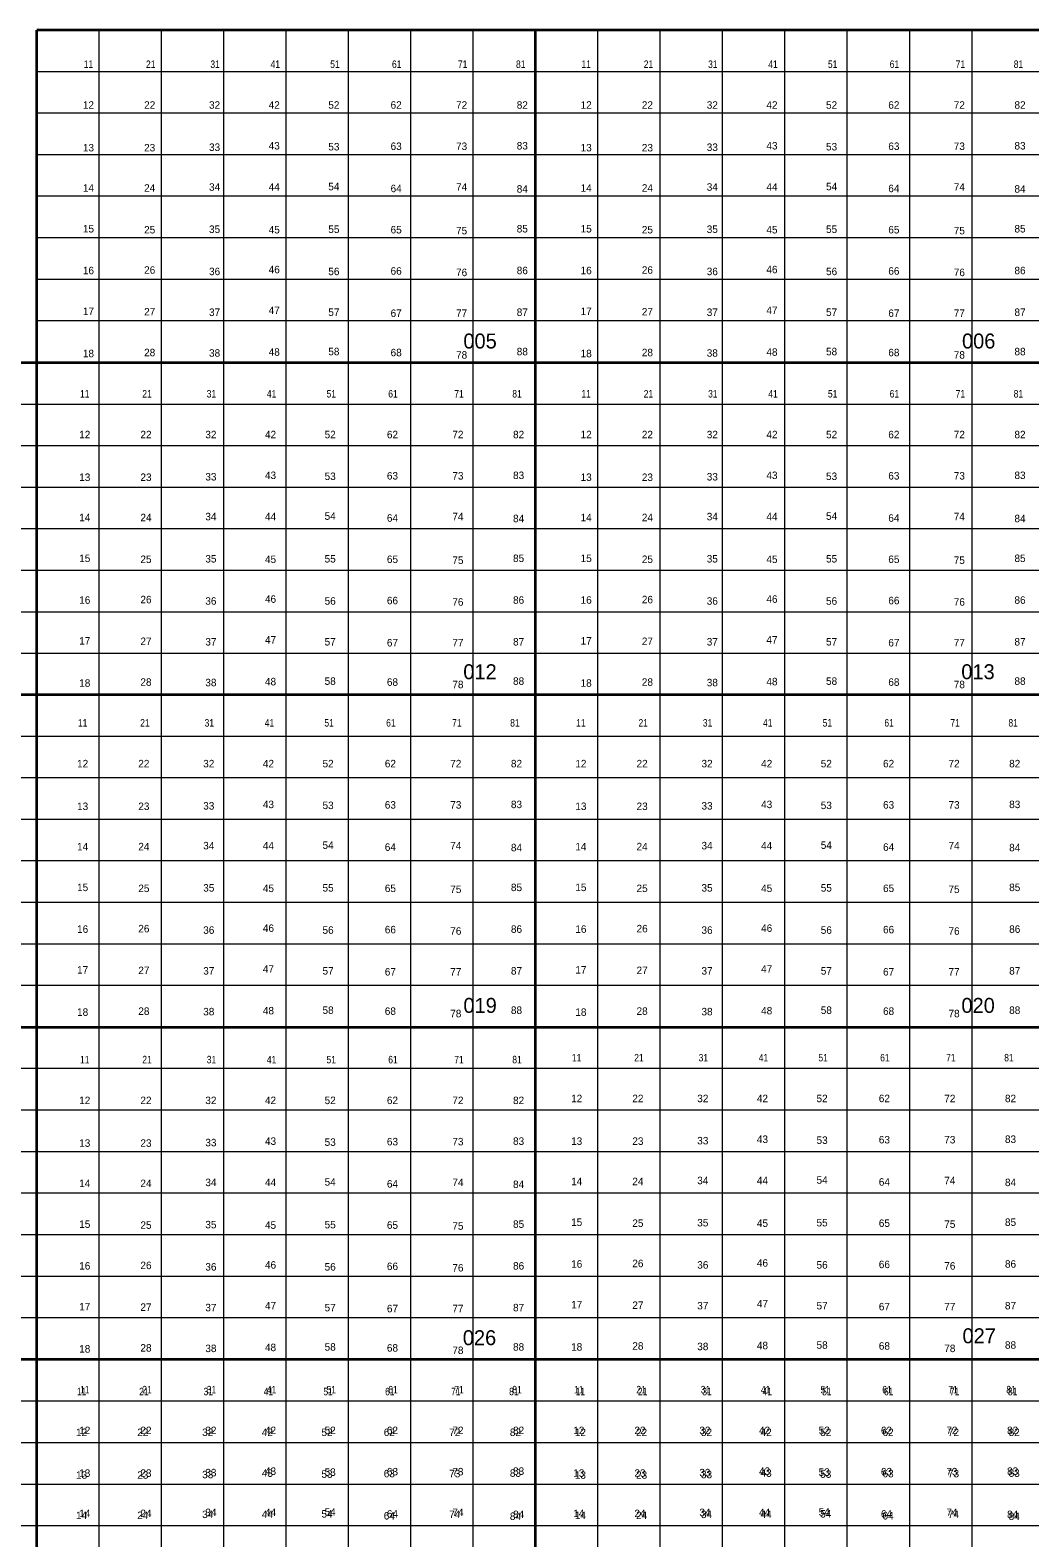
# Model space of a CAD drawing. Extents: x 639000 to 672000, y 222000 to 252000.
# Drawn here: x 647960 to 653973, y 242926 to 252000 of the extents above; entities that cross this region are included whole.
import ezdxf
from ezdxf.enums import TextEntityAlignment as Align

# ---------------------------------------------------------------- set-up
doc = ezdxf.new("R2010")
doc.units = 0
doc.header["$LTSCALE"] = 18
doc.layers.add('1', color=7, linetype='Continuous', lineweight=13)
doc.layers.add('2', color=7, linetype='Continuous')
doc.layers.add('29', color=7, linetype='Continuous')

msp = doc.modelspace()

# ---------------------------------------------------------------- linework, layer by layer
at = {"layer": '1', "lineweight": 35}
for p, q in [((657000, 252000), (648000, 252000)), ((648000, 224000), (648000, 252000)), ((651000, 224000), (651000, 252000)), ((645000, 250000), (657000, 250000)), ((660000, 248000), (639000, 248000)), ((639000, 246000), (663000, 246000)), ((666000, 244000), (639000, 244000))]:
    msp.add_line(p, q, dxfattribs=at)
at = {"layer": '1'}
for p, q in [((648375, 224000), (648375, 252000)), ((648750, 224000), (648750, 252000)), ((649125, 224000), (649125, 252000)), ((649500, 224000), (649500, 252000)), ((649875, 224000), (649875, 252000)), ((650250, 224000), (650250, 252000)), ((650625, 224000), (650625, 252000)), ((651375, 224000), (651375, 252000)), ((651750, 224000), (651750, 252000)), ((652125, 224000), (652125, 252000)), ((652500, 224000), (652500, 252000)), ((652875, 224000), (652875, 252000)), ((653250, 224000), (653250, 252000)), ((653625, 224000), (653625, 252000)), ((657000, 251750), (648000, 251750)), ((657000, 251500), (648000, 251500)), ((657000, 251250), (648000, 251250)), ((657000, 251000), (648000, 251000)), ((657000, 250750), (648000, 250750)), ((657000, 250500), (648000, 250500)), ((657000, 250250), (648000, 250250)), ((645000, 249750), (657000, 249750)), ((645000, 249500), (657000, 249500)), ((645000, 249250), (657000, 249250)), ((645000, 249000), (657000, 249000)), ((645000, 248750), (657000, 248750)), ((645000, 248500), (657000, 248500)), ((645000, 248250), (657000, 248250)), ((660000, 247750), (639000, 247750)), ((660000, 247500), (639000, 247500)), ((660000, 247250), (639000, 247250)), ((660000, 247000), (639000, 247000)), ((660000, 246750), (639000, 246750)), ((660000, 246500), (639000, 246500)), ((660000, 246250), (639000, 246250)), ((663000, 245750), (639000, 245750)), ((663000, 245500), (639000, 245500)), ((663000, 245250), (639000, 245250)), ((663000, 245000), (639000, 245000)), ((663000, 244750), (639000, 244750)), ((663000, 244500), (639000, 244500)), ((663000, 244250), (639000, 244250)), ((639000, 243750), (666000, 243750)), ((639000, 243500), (666000, 243500)), ((639000, 243250), (666000, 243250)), ((639000, 243000), (666000, 243000))]:
    msp.add_line(p, q, dxfattribs=at)

# ---------------------------------------------------------------- texts
at = {"layer": '2'}
for s, p in [('005', (650666.01, 250084.17)), ('006', (653665.16, 250084.17)), ('012', (650665.6, 248093.9)), ('013', (653660.9, 248093.9)), ('019', (650666.32, 246085.74)), ('020', (653661.69, 246085.74)), ('026', (650662.68, 244085.92))]:
    msp.add_text(s, height=90, dxfattribs=at).set_placement(p, align=Align.CENTER)
msp.add_text('027', height=90, rotation=359.94, dxfattribs=at).set_placement((653668.13, 244097.33), align=Align.CENTER)
at = {"layer": '29', "width": 0.85}
for s, p in [('11', (648310.53, 251772.53)), ('21', (648685.14, 251772.53)), ('31', (649072.44, 251772.53)), ('41', (649434.34, 251772.53)), ('51', (649793.08, 251772.53)), ('61', (650164.5, 251772.53)), ('71', (650561.33, 251772.53)), ('81', (650910.54, 251772.53)), ('11', (651304.19, 251772.53)), ('21', (651678.79, 251772.53)), ('31', (652066.09, 251772.53)), ('41', (652428, 251772.53)), ('51', (652786.73, 251772.53)), ('61', (653158.16, 251772.53)), ('71', (653554.98, 251772.53)), ('81', (653904.19, 251772.53)), ('11', (648288.31, 249789.2)), ('21', (648662.92, 249789.2)), ('31', (649050.22, 249789.2)), ('41', (649412.12, 249789.2)), ('51', (649770.85, 249789.2)), ('61', (650142.28, 249789.2)), ('71', (650539.11, 249789.2)), ('81', (650888.32, 249789.2)), ('11', (651304.19, 249789.2)), ('21', (651678.79, 249789.2)), ('31', (652066.09, 249789.2)), ('41', (652428, 249789.2)), ('51', (652786.73, 249789.2)), ('61', (653158.16, 249789.2)), ('71', (653554.98, 249789.2)), ('81', (653904.19, 249789.2)), ('11', (648275.61, 247808.76)), ('21', (648650.22, 247808.76)), ('31', (649037.52, 247808.76)), ('41', (649399.42, 247808.76)), ('51', (649758.15, 247808.76)), ('61', (650129.58, 247808.76)), ('71', (650526.41, 247808.76)), ('81', (650875.62, 247808.76)), ('11', (651272.44, 247808.76)), ('21', (651647.05, 247808.76)), ('31', (652034.35, 247808.76)), ('41', (652396.25, 247808.76)), ('51', (652754.98, 247808.76)), ('61', (653126.41, 247808.76)), ('71', (653523.24, 247808.76)), ('81', (653872.45, 247808.76)), ('11', (648288.31, 245782.12)), ('21', (648662.92, 245782.12)), ('31', (649050.22, 245782.12)), ('41', (649412.12, 245782.12)), ('51', (649770.85, 245782.12)), ('61', (650142.28, 245782.12)), ('71', (650539.11, 245782.12)), ('81', (650888.32, 245782.12)), ('11', (651247.05, 245793.67)), ('21', (651621.65, 245793.67)), ('31', (652008.95, 245793.67)), ('41', (652370.86, 245793.67)), ('51', (652729.59, 245793.67)), ('61', (653101.02, 245793.67)), ('71', (653497.84, 245793.67)), ('81', (653847.05, 245793.67)), ('11', (648269.26, 243784.35)), ('11', (648288.31, 243795.9)), ('21', (648643.86, 243784.35)), ('21', (648662.92, 243795.9)), ('31', (649031.16, 243784.35)), ('31', (649050.22, 243795.9)), ('41', (649393.07, 243784.35)), ('41', (649412.12, 243795.9)), ('51', (649751.8, 243784.35)), ('51', (649770.85, 243795.9)), ('61', (650123.23, 243784.35)), ('61', (650142.28, 243795.9)), ('71', (650520.05, 243784.35)), ('71', (650539.11, 243795.9)), ('81', (650869.26, 243784.35)), ('81', (650888.32, 243795.9)), ('11', (651259.74, 243795.9)), ('11', (651269.26, 243784.35)), ('21', (651634.35, 243795.9)), ('21', (651643.86, 243784.35)), ('31', (652021.65, 243795.9)), ('31', (652031.16, 243784.35)), ('41', (652383.55, 243795.9)), ('41', (652393.07, 243784.35)), ('51', (652742.29, 243795.9)), ('51', (652751.8, 243784.35)), ('61', (653113.71, 243795.9)), ('61', (653123.23, 243784.35)), ('71', (653510.54, 243795.9)), ('71', (653520.05, 243784.35)), ('81', (653859.75, 243795.9)), ('81', (653869.26, 243784.35))]:
    msp.add_text(s, height=45, dxfattribs=at).set_placement(p, align=Align.CENTER)
at = {"layer": '29'}
for s, p in [('12', (648310.53, 251527.14)), ('22', (648678.79, 251527.14)), ('32', (649069.26, 251527.14)), ('42', (649427.99, 251527.14)), ('52', (649786.72, 251527.14)), ('62', (650161.33, 251527.14)), ('72', (650554.98, 251527.14)), ('82', (650920.06, 251527.14)), ('12', (651304.19, 251527.14)), ('22', (651672.44, 251527.14)), ('32', (652062.92, 251527.14)), ('42', (652421.65, 251527.14)), ('52', (652780.38, 251527.14)), ('62', (653154.98, 251527.14)), ('72', (653548.63, 251527.14)), ('82', (653913.71, 251527.14)), ('13', (648310.53, 251270.2)), ('23', (648678.79, 251270.2)), ('33', (649069.26, 251273.09)), ('43', (649427.99, 251281.75)), ('53', (649786.72, 251275.98)), ('63', (650161.33, 251278.86)), ('73', (650554.98, 251278.86)), ('83', (650920.06, 251281.75)), ('13', (651304.19, 251270.2)), ('23', (651672.44, 251270.2)), ('33', (652062.92, 251273.09)), ('43', (652421.65, 251281.75)), ('53', (652780.38, 251275.98)), ('63', (653154.98, 251278.86)), ('73', (653548.63, 251278.86)), ('83', (653913.71, 251281.75)), ('14', (648310.53, 251027.7)), ('24', (648678.79, 251027.7)), ('34', (649069.26, 251033.48)), ('44', (649427.99, 251033.48)), ('54', (649786.72, 251036.36)), ('64', (650161.33, 251024.81)), ('74', (650554.98, 251033.48)), ('14', (651304.19, 251027.7)), ('24', (651672.44, 251027.7)), ('34', (652062.92, 251033.48)), ('44', (652421.65, 251033.48)), ('54', (652780.38, 251036.36)), ('64', (653154.98, 251024.81)), ('74', (653548.63, 251033.48)), ('84', (650920.06, 251021.93)), ('84', (653913.71, 251021.93)), ('15', (648310.53, 250782.31)), ('25', (648678.79, 250776.54)), ('35', (649069.26, 250779.42)), ('45', (649427.99, 250776.54)), ('55', (649786.72, 250779.42)), ('65', (650161.33, 250776.54)), ('75', (650554.98, 250770.76)), ('85', (650920.06, 250782.31)), ('15', (651304.19, 250782.31)), ('25', (651672.44, 250776.54)), ('35', (652062.92, 250779.42)), ('45', (652421.65, 250776.54)), ('55', (652780.38, 250779.42)), ('65', (653154.98, 250776.54)), ('75', (653548.63, 250770.76)), ('85', (653913.71, 250782.31)), ('16', (648310.53, 250531.15)), ('26', (648678.79, 250534.03)), ('36', (649069.26, 250525.37)), ('46', (649427.99, 250536.92)), ('56', (649786.72, 250525.37)), ('66', (650161.33, 250528.26)), ('76', (650554.98, 250519.6)), ('86', (650920.06, 250531.15)), ('16', (651304.19, 250531.15)), ('26', (651672.44, 250534.03)), ('36', (652062.92, 250525.37)), ('46', (652421.65, 250536.92)), ('56', (652780.38, 250525.37)), ('66', (653154.98, 250528.26)), ('76', (653548.63, 250519.6)), ('86', (653913.71, 250531.15)), ('17', (648310.53, 250285.76)), ('27', (648678.79, 250282.87)), ('37', (649069.26, 250279.98)), ('47', (649428, 250291.53)), ('57', (649786.73, 250279.98)), ('67', (650161.33, 250274.21)), ('77', (650554.98, 250274.21)), ('87', (650920.06, 250279.98)), ('17', (651304.19, 250285.76)), ('27', (651672.44, 250282.87)), ('37', (652062.92, 250279.98)), ('47', (652421.65, 250291.53)), ('57', (652780.38, 250279.98)), ('67', (653154.98, 250274.21)), ('77', (653548.63, 250274.21)), ('87', (653913.71, 250279.98)), ('18', (648310.53, 250031.7)), ('28', (648678.79, 250037.48)), ('38', (649069.26, 250034.59)), ('48', (649427.99, 250040.36)), ('58', (649786.72, 250043.25)), ('68', (650161.33, 250037.48)), ('88', (650920.06, 250043.25)), ('18', (651304.19, 250031.7)), ('28', (651672.44, 250037.48)), ('38', (652062.92, 250034.59)), ('48', (652421.65, 250040.36)), ('58', (652780.38, 250043.25)), ('68', (653154.98, 250037.48)), ('88', (653913.71, 250043.25)), ('78', (650554.98, 250023.04)), ('78', (653548.63, 250023.04)), ('12', (648288.31, 249543.81)), ('22', (648656.57, 249543.81)), ('32', (649047.04, 249543.81)), ('42', (649405.77, 249543.81)), ('52', (649764.5, 249543.81)), ('62', (650139.11, 249543.81)), ('72', (650532.76, 249543.81)), ('82', (650897.84, 249543.81)), ('12', (651304.19, 249543.81)), ('22', (651672.44, 249543.81)), ('32', (652062.92, 249543.81)), ('42', (652421.65, 249543.81)), ('52', (652780.38, 249543.81)), ('62', (653154.98, 249543.81)), ('72', (653548.63, 249543.81)), ('82', (653913.71, 249543.81)), ('13', (648288.31, 249286.87)), ('23', (648656.57, 249286.87)), ('33', (649047.04, 249289.76)), ('43', (649405.77, 249298.42)), ('53', (649764.5, 249292.65)), ('63', (650139.11, 249295.53)), ('73', (650532.76, 249295.53)), ('83', (650897.84, 249298.42)), ('13', (651304.19, 249286.87)), ('23', (651672.44, 249286.87)), ('33', (652062.92, 249289.76)), ('43', (652421.65, 249298.42)), ('53', (652780.38, 249292.65)), ('63', (653154.98, 249295.53)), ('73', (653548.63, 249295.53)), ('83', (653913.71, 249298.42)), ('14', (648288.31, 249044.37)), ('24', (648656.57, 249044.37)), ('34', (649047.04, 249050.14)), ('44', (649405.77, 249050.14)), ('54', (649764.5, 249053.03)), ('64', (650139.11, 249041.48)), ('74', (650532.76, 249050.14)), ('84', (650897.84, 249038.6)), ('14', (651304.19, 249044.37)), ('24', (651672.44, 249044.37)), ('34', (652062.92, 249050.14)), ('44', (652421.65, 249050.14)), ('54', (652780.38, 249053.03)), ('64', (653154.98, 249041.48)), ('74', (653548.63, 249050.14)), ('84', (653913.71, 249038.6)), ('15', (648288.31, 248798.98)), ('25', (648656.57, 248793.2)), ('35', (649047.04, 248796.09)), ('45', (649405.77, 248793.2)), ('55', (649764.5, 248796.09)), ('65', (650139.11, 248793.21)), ('75', (650532.76, 248787.43)), ('85', (650897.84, 248798.98)), ('15', (651304.19, 248798.98)), ('25', (651672.44, 248793.2)), ('35', (652062.92, 248796.09)), ('45', (652421.65, 248793.2)), ('55', (652780.38, 248796.09)), ('65', (653154.98, 248793.21)), ('75', (653548.63, 248787.43)), ('85', (653913.71, 248798.98)), ('16', (648288.31, 248547.81)), ('26', (648656.57, 248550.7)), ('36', (649047.04, 248542.04)), ('46', (649405.77, 248553.59)), ('56', (649764.5, 248542.04)), ('66', (650139.11, 248544.93)), ('76', (650532.76, 248536.27)), ('86', (650897.84, 248547.81)), ('16', (651304.19, 248547.81)), ('26', (651672.44, 248550.7)), ('36', (652062.92, 248542.04)), ('46', (652421.65, 248553.59)), ('56', (652780.38, 248542.04)), ('66', (653154.98, 248544.93)), ('76', (653548.63, 248536.27)), ('86', (653913.71, 248547.81)), ('17', (648288.31, 248302.42)), ('47', (649405.77, 248308.2)), ('17', (651304.19, 248302.42)), ('47', (652421.65, 248308.2)), ('27', (648656.57, 248299.54)), ('37', (649047.04, 248296.65)), ('57', (649764.5, 248296.65)), ('67', (650139.11, 248290.88)), ('77', (650532.76, 248290.88)), ('87', (650897.84, 248296.65)), ('27', (651672.44, 248299.54)), ('37', (652062.92, 248296.65)), ('57', (652780.38, 248296.65)), ('67', (653154.98, 248290.88)), ('77', (653548.63, 248290.88)), ('87', (653913.71, 248296.65)), ('18', (648288.31, 248048.37)), ('28', (648656.57, 248054.15)), ('38', (649047.04, 248051.26)), ('48', (649405.77, 248057.03)), ('58', (649764.5, 248059.92)), ('68', (650139.11, 248054.15)), ('78', (650532.76, 248039.71)), ('88', (650897.84, 248059.92)), ('18', (651304.19, 248048.37)), ('28', (651672.44, 248054.15)), ('38', (652062.92, 248051.26)), ('48', (652421.65, 248057.03)), ('58', (652780.38, 248059.92)), ('68', (653154.98, 248054.15)), ('78', (653548.63, 248039.71)), ('88', (653913.71, 248059.92)), ('12', (648275.61, 247563.36)), ('22', (648643.87, 247563.36)), ('32', (649034.34, 247563.36)), ('42', (649393.07, 247563.36)), ('52', (649751.8, 247563.36)), ('62', (650126.41, 247563.36)), ('72', (650520.06, 247563.36)), ('82', (650885.14, 247563.36)), ('12', (651272.44, 247563.36)), ('22', (651640.7, 247563.36)), ('32', (652031.17, 247563.36)), ('42', (652389.9, 247563.36)), ('52', (652748.63, 247563.36)), ('62', (653123.24, 247563.36)), ('72', (653516.89, 247563.36)), ('82', (653881.97, 247563.36)), ('13', (648275.61, 247306.43)), ('23', (648643.87, 247306.43)), ('33', (649034.34, 247309.31)), ('43', (649393.07, 247317.97)), ('53', (649751.8, 247312.2)), ('63', (650126.41, 247315.09)), ('73', (650520.06, 247315.09)), ('83', (650885.14, 247317.97)), ('13', (651272.44, 247306.43)), ('23', (651640.7, 247306.43)), ('33', (652031.17, 247309.31)), ('43', (652389.9, 247317.97)), ('53', (652748.63, 247312.2)), ('63', (653123.24, 247315.09)), ('73', (653516.89, 247315.09)), ('83', (653881.97, 247317.97)), ('14', (648275.61, 247063.92)), ('24', (648643.87, 247063.92)), ('34', (649034.34, 247069.7)), ('44', (649393.07, 247069.7)), ('54', (649751.8, 247072.58)), ('64', (650126.41, 247061.04)), ('74', (650520.06, 247069.7)), ('84', (650885.14, 247058.15)), ('14', (651272.44, 247063.92)), ('24', (651640.7, 247063.92)), ('34', (652031.17, 247069.7)), ('44', (652389.9, 247069.7)), ('54', (652748.63, 247072.58)), ('64', (653123.24, 247061.04)), ('74', (653516.89, 247069.7)), ('84', (653881.97, 247058.15)), ('15', (648275.61, 246818.53)), ('25', (648643.87, 246812.76)), ('35', (649034.34, 246815.65)), ('45', (649393.07, 246812.76)), ('55', (649751.8, 246815.65)), ('65', (650126.41, 246812.76)), ('75', (650520.06, 246806.98)), ('85', (650885.14, 246818.53)), ('15', (651272.44, 246818.53)), ('25', (651640.7, 246812.76)), ('35', (652031.17, 246815.65)), ('45', (652389.9, 246812.76)), ('55', (652748.63, 246815.65)), ('65', (653123.24, 246812.76)), ('75', (653516.89, 246806.98)), ('85', (653881.97, 246818.53)), ('16', (648275.61, 246567.37)), ('26', (648643.87, 246570.26)), ('36', (649034.34, 246561.59)), ('46', (649393.07, 246573.14)), ('56', (649751.8, 246561.6)), ('66', (650126.41, 246564.48)), ('76', (650520.06, 246555.82)), ('86', (650885.14, 246567.37)), ('16', (651272.44, 246567.37)), ('26', (651640.7, 246570.26)), ('36', (652031.17, 246561.59)), ('46', (652389.9, 246573.14)), ('56', (652748.63, 246561.6)), ('66', (653123.24, 246564.48)), ('76', (653516.89, 246555.82)), ('86', (653881.97, 246567.37)), ('17', (648275.61, 246321.98)), ('27', (648643.87, 246319.09)), ('37', (649034.34, 246316.2)), ('47', (649393.07, 246327.75)), ('57', (649751.8, 246316.2)), ('67', (650126.41, 246310.43)), ('77', (650520.06, 246310.43)), ('87', (650885.14, 246316.2)), ('17', (651272.44, 246321.98)), ('27', (651640.7, 246319.09)), ('37', (652031.17, 246316.2)), ('47', (652389.9, 246327.75)), ('57', (652748.63, 246316.2)), ('67', (653123.24, 246310.43)), ('77', (653516.89, 246310.43)), ('87', (653881.97, 246316.2)), ('18', (648275.61, 246067.93)), ('28', (648643.87, 246073.7)), ('38', (649034.34, 246070.81)), ('48', (649393.07, 246076.59)), ('58', (649751.8, 246079.48)), ('68', (650126.41, 246073.7)), ('78', (650520.06, 246059.27)), ('88', (650885.14, 246079.47)), ('18', (651272.44, 246067.93)), ('28', (651640.7, 246073.7)), ('38', (652031.17, 246070.81)), ('48', (652389.9, 246076.59)), ('58', (652748.63, 246079.48)), ('68', (653123.24, 246073.7)), ('78', (653516.89, 246059.27)), ('88', (653881.97, 246079.47)), ('12', (648288.31, 245536.73)), ('22', (648656.57, 245536.73)), ('32', (649047.04, 245536.73)), ('42', (649405.77, 245536.73)), ('52', (649764.5, 245536.73)), ('62', (650139.11, 245536.73)), ('72', (650532.76, 245536.73)), ('82', (650897.84, 245536.73)), ('12', (651247.04, 245548.28)), ('22', (651615.3, 245548.28)), ('32', (652005.78, 245548.28)), ('42', (652364.51, 245548.28)), ('52', (652723.24, 245548.28)), ('62', (653097.84, 245548.28)), ('72', (653491.49, 245548.28)), ('82', (653856.57, 245548.28)), ('13', (648288.31, 245279.79)), ('23', (648656.57, 245279.79)), ('33', (649047.04, 245282.68)), ('43', (649405.77, 245291.34)), ('53', (649764.5, 245285.56)), ('63', (650139.11, 245288.45)), ('73', (650532.76, 245288.45)), ('83', (650897.84, 245291.34)), ('13', (651247.05, 245291.34)), ('23', (651615.3, 245291.34)), ('33', (652005.78, 245294.22)), ('43', (652364.51, 245302.89)), ('53', (652723.24, 245297.11)), ('63', (653097.84, 245300)), ('73', (653491.49, 245300)), ('83', (653856.57, 245302.89)), ('14', (648288.31, 245037.29)), ('24', (648656.57, 245037.29)), ('34', (649047.04, 245043.06)), ('44', (649405.77, 245043.06)), ('54', (649764.5, 245045.95)), ('64', (650139.11, 245034.4)), ('74', (650532.76, 245043.06)), ('14', (651247.05, 245048.83)), ('24', (651615.3, 245048.83)), ('34', (652005.78, 245054.61)), ('44', (652364.51, 245054.61)), ('54', (652723.24, 245057.49)), ('64', (653097.84, 245045.95)), ('74', (653491.49, 245054.61)), ('84', (653856.57, 245043.06)), ('84', (650897.84, 245031.51)), ('15', (648288.31, 244791.9)), ('25', (648656.57, 244786.12)), ('35', (649047.04, 244789.01)), ('45', (649405.77, 244786.12)), ('55', (649764.5, 244789.01)), ('65', (650139.11, 244786.12)), ('75', (650532.76, 244780.35)), ('85', (650897.84, 244791.9)), ('15', (651247.05, 244803.44)), ('25', (651615.3, 244797.67)), ('35', (652005.78, 244800.56)), ('45', (652364.51, 244797.67)), ('55', (652723.24, 244800.56)), ('65', (653097.84, 244797.67)), ('75', (653491.49, 244791.9)), ('85', (653856.57, 244803.44)), ('16', (648288.31, 244540.73)), ('26', (648656.57, 244543.62)), ('36', (649047.04, 244534.96)), ('46', (649405.77, 244546.51)), ('56', (649764.5, 244534.96)), ('66', (650139.11, 244537.84)), ('76', (650532.76, 244529.18)), ('86', (650897.84, 244540.73)), ('16', (651247.05, 244552.28)), ('26', (651615.3, 244555.17)), ('36', (652005.78, 244546.51)), ('46', (652364.51, 244558.05)), ('56', (652723.24, 244546.51)), ('66', (653097.84, 244549.39)), ('76', (653491.49, 244540.73)), ('86', (653856.57, 244552.28)), ('47', (652364.51, 244312.66)), ('17', (648288.31, 244295.34)), ('27', (648656.57, 244292.45)), ('37', (649047.04, 244289.57)), ('47', (649405.77, 244301.11)), ('57', (649764.5, 244289.57)), ('67', (650139.11, 244283.79)), ('77', (650532.76, 244283.79)), ('87', (650897.84, 244289.57)), ('17', (651247.05, 244306.89)), ('27', (651615.3, 244304)), ('37', (652005.78, 244301.11)), ('57', (652723.24, 244301.11)), ('67', (653097.84, 244295.34)), ('77', (653491.49, 244295.34)), ('87', (653856.57, 244301.11)), ('18', (648288.31, 244041.29)), ('28', (648656.57, 244047.06)), ('38', (649047.04, 244044.18)), ('48', (649405.77, 244049.95)), ('58', (649764.5, 244052.84)), ('68', (650139.11, 244047.06)), ('88', (650897.84, 244052.84)), ('18', (651247.04, 244052.84)), ('28', (651615.3, 244058.61)), ('38', (652005.78, 244055.72)), ('48', (652364.51, 244061.5)), ('58', (652723.24, 244064.39)), ('68', (653097.84, 244058.61)), ('78', (653491.49, 244044.18)), ('88', (653856.57, 244064.39)), ('78', (650532.76, 244032.63)), ('12', (648269.25, 243538.96)), ('12', (648288.31, 243550.51)), ('22', (648637.51, 243538.96)), ('22', (648656.57, 243550.51)), ('32', (649027.99, 243538.96)), ('32', (649047.04, 243550.51)), ('42', (649386.72, 243538.96)), ('42', (649405.77, 243550.51)), ('52', (649745.45, 243538.96)), ('52', (649764.5, 243550.51)), ('62', (650120.05, 243538.96)), ('62', (650139.11, 243550.51)), ('72', (650513.7, 243538.96)), ('72', (650532.76, 243550.51)), ('82', (650878.78, 243538.96)), ('82', (650897.84, 243550.51)), ('12', (651259.74, 243550.51)), ('12', (651269.25, 243538.96)), ('22', (651628, 243550.51)), ('22', (651637.51, 243538.96)), ('32', (652018.47, 243550.51)), ('32', (652027.99, 243538.96)), ('42', (652377.2, 243550.51)), ('42', (652386.72, 243538.96)), ('52', (652735.93, 243550.51)), ('52', (652745.45, 243538.96)), ('62', (653110.54, 243550.51)), ('62', (653120.05, 243538.96)), ('72', (653504.19, 243550.51)), ('72', (653513.7, 243538.96)), ('82', (653869.27, 243550.51)), ('82', (653878.78, 243538.96)), ('13', (648269.26, 243282.02)), ('13', (648288.31, 243293.57)), ('23', (648637.51, 243282.02)), ('23', (648656.57, 243293.57)), ('33', (649027.99, 243284.91)), ('33', (649047.04, 243296.46)), ('43', (649386.72, 243293.57)), ('43', (649405.77, 243305.12)), ('53', (649745.45, 243287.8)), ('53', (649764.5, 243299.35)), ('63', (650120.05, 243290.68)), ('63', (650139.11, 243302.23)), ('73', (650513.7, 243290.68)), ('73', (650532.76, 243302.23)), ('83', (650878.78, 243293.57)), ('83', (650897.84, 243305.12)), ('13', (651259.74, 243293.57)), ('13', (651269.26, 243282.02)), ('23', (651628, 243293.57)), ('23', (651637.51, 243282.02)), ('33', (652018.47, 243296.46)), ('33', (652027.99, 243284.91)), ('43', (652377.2, 243305.12)), ('43', (652386.72, 243293.57)), ('53', (652735.94, 243299.35)), ('53', (652745.45, 243287.8)), ('63', (653110.54, 243302.23)), ('63', (653120.05, 243290.68)), ('73', (653504.19, 243302.23)), ('73', (653513.7, 243290.68)), ('83', (653869.27, 243305.12)), ('83', (653878.78, 243293.57)), ('14', (648269.26, 243039.52)), ('14', (648288.31, 243051.07)), ('24', (648637.51, 243039.52)), ('24', (648656.57, 243051.07)), ('34', (649027.99, 243045.29)), ('34', (649047.04, 243056.84)), ('44', (649386.72, 243045.29)), ('44', (649405.77, 243056.84)), ('54', (649745.45, 243048.18)), ('54', (649764.5, 243059.73)), ('64', (650139.11, 243048.18)), ('74', (650513.7, 243045.29)), ('74', (650532.76, 243056.84)), ('84', (650897.84, 243045.29)), ('14', (651259.74, 243051.07)), ('14', (651269.26, 243039.52)), ('24', (651628, 243051.07)), ('24', (651637.51, 243039.52)), ('34', (652018.47, 243056.84)), ('34', (652027.99, 243045.29)), ('44', (652377.2, 243056.84)), ('44', (652386.72, 243045.29)), ('54', (652735.94, 243059.73)), ('54', (652745.45, 243048.18)), ('64', (653110.54, 243048.18)), ('74', (653504.19, 243056.84)), ('74', (653513.7, 243045.29)), ('84', (653869.27, 243045.29)), ('64', (650120.05, 243036.63)), ('84', (650878.78, 243033.74)), ('64', (653120.05, 243036.63)), ('84', (653878.78, 243033.74))]:
    msp.add_text(s, height=45, dxfattribs=at).set_placement(p, align=Align.CENTER)

doc.saveas('drawing.dxf')
